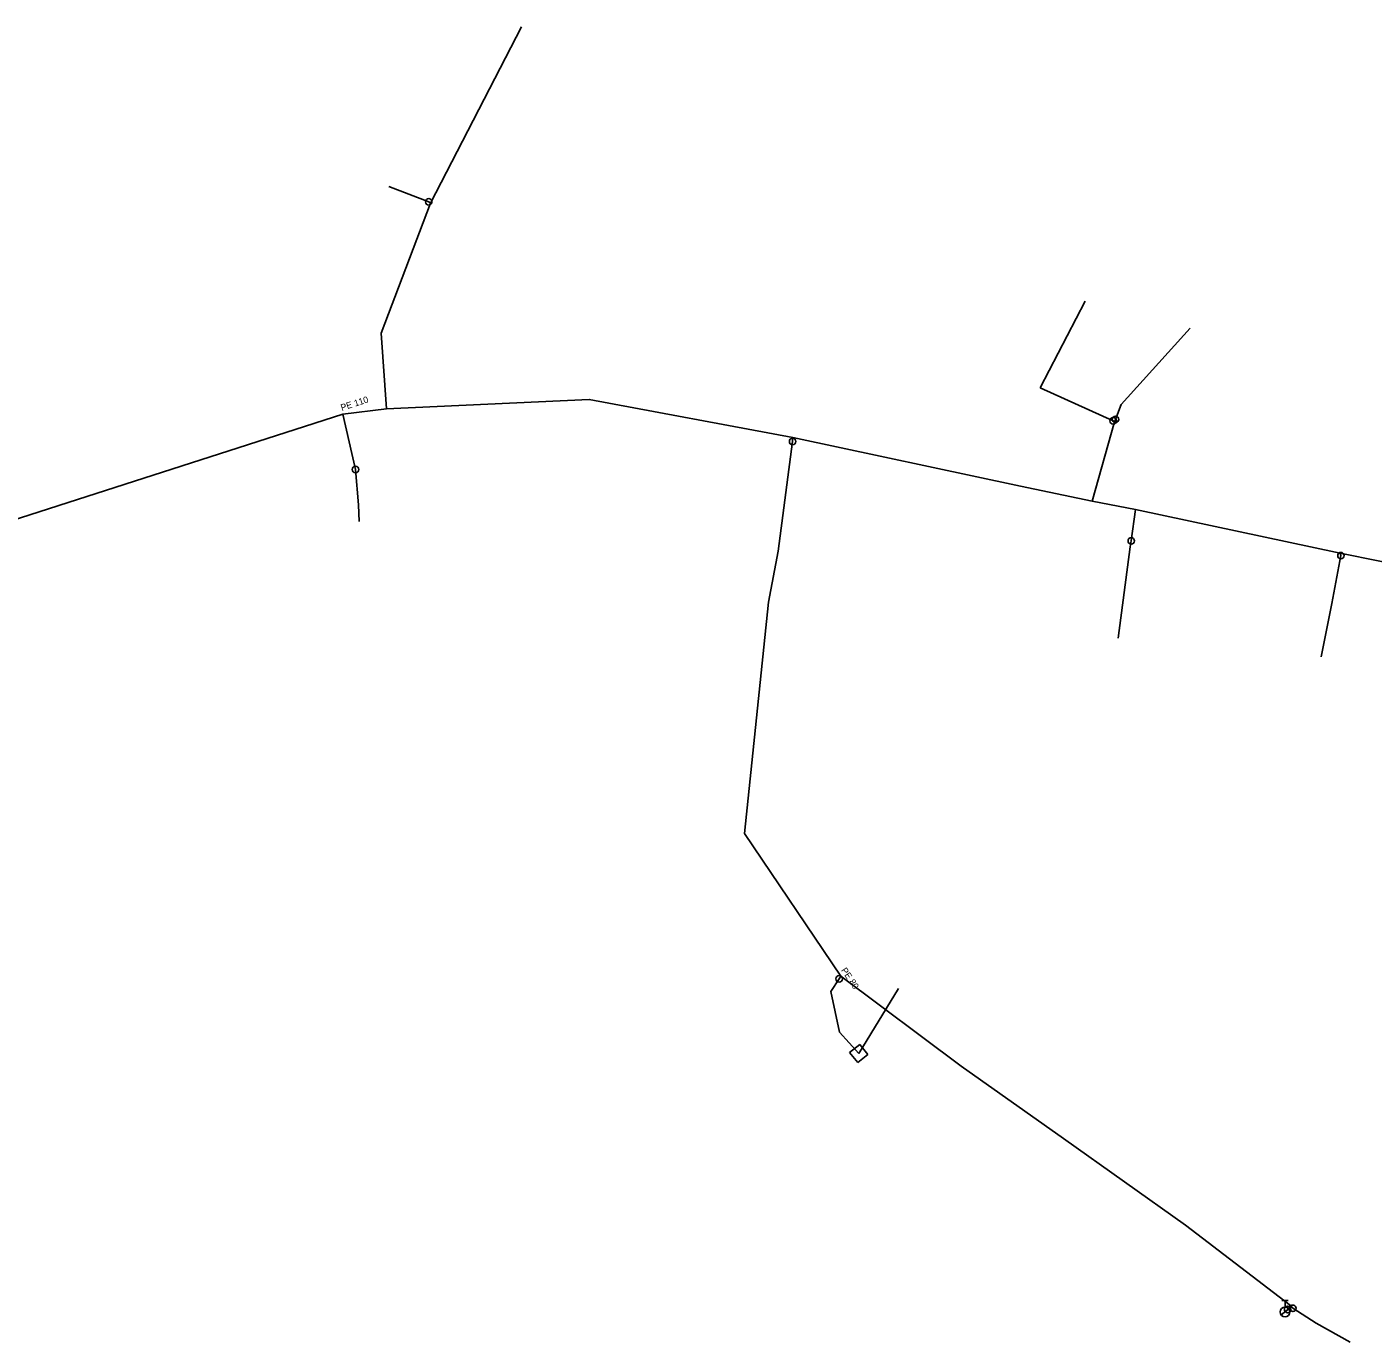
# Model space of a CAD drawing. Extents: x -681947 to -681511, y -1163527 to -1163073.
# Drawn here: x -681767.6 to -681664, y -1163510.7 to -1163409.5 of the extents above; entities that cross this region are included whole.
import ezdxf

# ---------------------------------------------------------------- set-up
doc = ezdxf.new("R2010")
doc.units = 0
for name, color, linetype in [('Hydranty', 7, 'Continuous'), ('Popis vodovodních řadů', 7, 'Continuous'), ('Vod přípojky-voda pitná', 7, 'Continuous'), ('Vodovodní řad', 7, 'Continuous'), ('Vodovodní šachty', 7, 'Continuous'), ('Vodovodní šoupata', 7, 'Continuous')]:
    doc.layers.add(name, color=color, linetype=linetype)

msp = doc.modelspace()

# ---------------------------------------------------------------- linework, layer by layer
at = {"layer": 'Hydranty'}
for p, q in [((-681671.04, -1163507.53), (-681670.54, -1163507.53)), ((-681670.79, -1163508.03), (-681670.79, -1163507.53)), ((-681671.08, -1163508.63), (-681670.49, -1163508.17))]:
    msp.add_line(p, q, dxfattribs=at)
msp.add_circle((-681670.79, -1163508.4), 0.375, dxfattribs=at)
at = {"layer": 'Vod přípojky-voda pitná'}
for points in [[(-681736.55, -1163423.04), (-681729.55, -1163409.48)], [(-681736.55, -1163423.04), (-681736.68, -1163422.95), (-681739.76, -1163421.77)], [(-681739.93, -1163438.87), (-681740.35, -1163433.05), (-681736.55, -1163423.04)], [(-681689.62, -1163437.27), (-681686.17, -1163430.59)], [(-681683.39, -1163438.55), (-681678.09, -1163432.68)], [(-681683.9, -1163439.89), (-681684.02, -1163439.8), (-681689.62, -1163437.27)], [(-681743.28, -1163439.28), (-681742.31, -1163443.55), (-681742.08, -1163446.26)], [(-681683.9, -1163439.89), (-681683.84, -1163439.69), (-681683.39, -1163438.55)], [(-681685.63, -1163445.99), (-681683.9, -1163439.89)], [(-681742.08, -1163446.26), (-681742.03, -1163447.54)], [(-681682.3, -1163446.63), (-681682.62, -1163449.05), (-681682.7, -1163449.51)], [(-681682.7, -1163449.51), (-681683.62, -1163456.54)], [(-681666.54, -1163450), (-681666.49, -1163450.18), (-681667.2, -1163453.86)], [(-681667.2, -1163453.86), (-681668, -1163457.96)], [(-681704.97, -1163482.55), (-681705.1, -1163482.76), (-681705.74, -1163483.72), (-681705.06, -1163486.87), (-681703.59, -1163488.5)], [(-681700.53, -1163483.51), (-681703.59, -1163488.5)], [(-681670.38, -1163507.91), (-681670.18, -1163508.12), (-681668.39, -1163509.26), (-681665.77, -1163510.72)]]:
    msp.add_lwpolyline(points, dxfattribs=at)
at = {"layer": 'Vodovodní řad'}
for points in [[(-681776.58, -1163449.84), (-681772.96, -1163448.87), (-681772.51, -1163448.69), (-681743.28, -1163439.28), (-681739.93, -1163438.87), (-681724.33, -1163438.15), (-681708.67, -1163441.09)], [(-681708.68, -1163441.4), (-681709.8, -1163449.84), (-681710.54, -1163453.77), (-681712.37, -1163471.56), (-681704.97, -1163482.55), (-681695.7, -1163489.48), (-681687.83, -1163495.06), (-681678.46, -1163501.71), (-681670.38, -1163507.91)], [(-681708.67, -1163441.09), (-681708.68, -1163441.4)], [(-681708.67, -1163441.09), (-681691.14, -1163444.83), (-681685.63, -1163445.99), (-681682.3, -1163446.63), (-681666.54, -1163450), (-681639.07, -1163455.52), (-681630.97, -1163457.38), (-681603.46, -1163463.79)], [(-681670.59, -1163508.21), (-681670.79, -1163508.4)], [(-681670.38, -1163507.91), (-681670.59, -1163508.21)]]:
    msp.add_lwpolyline(points, dxfattribs=at)
at = {"layer": 'Vodovodní šachty'}
for p, q in [((-681703.51, -1163487.8), (-681704.29, -1163488.42)), ((-681702.89, -1163488.58), (-681703.51, -1163487.8)), ((-681704.29, -1163488.42), (-681703.67, -1163489.2)), ((-681703.67, -1163489.2), (-681702.89, -1163488.58))]:
    msp.add_line(p, q, dxfattribs=at)
at = {"layer": 'Vodovodní šoupata'}
for centre in [(-681736.68, -1163422.95), (-681684.02, -1163439.8), (-681683.84, -1163439.69), (-681708.68, -1163441.4), (-681742.31, -1163443.55), (-681682.62, -1163449.05), (-681666.49, -1163450.18), (-681705.1, -1163482.76), (-681670.59, -1163508.21), (-681670.18, -1163508.12)]:
    msp.add_circle(centre, 0.25, dxfattribs=at)

# ---------------------------------------------------------------- texts
at = {"layer": 'Popis vodovodních řadů'}
for s, rotation, p in [('PE 110', 17.8449, (-681743.36, -1163439.04)), ('PE 80', 303.9539, (-681704.97, -1163482.1))]:
    msp.add_text(s, height=0.5, rotation=rotation, dxfattribs=at).set_placement(p)

doc.saveas('drawing.dxf')
